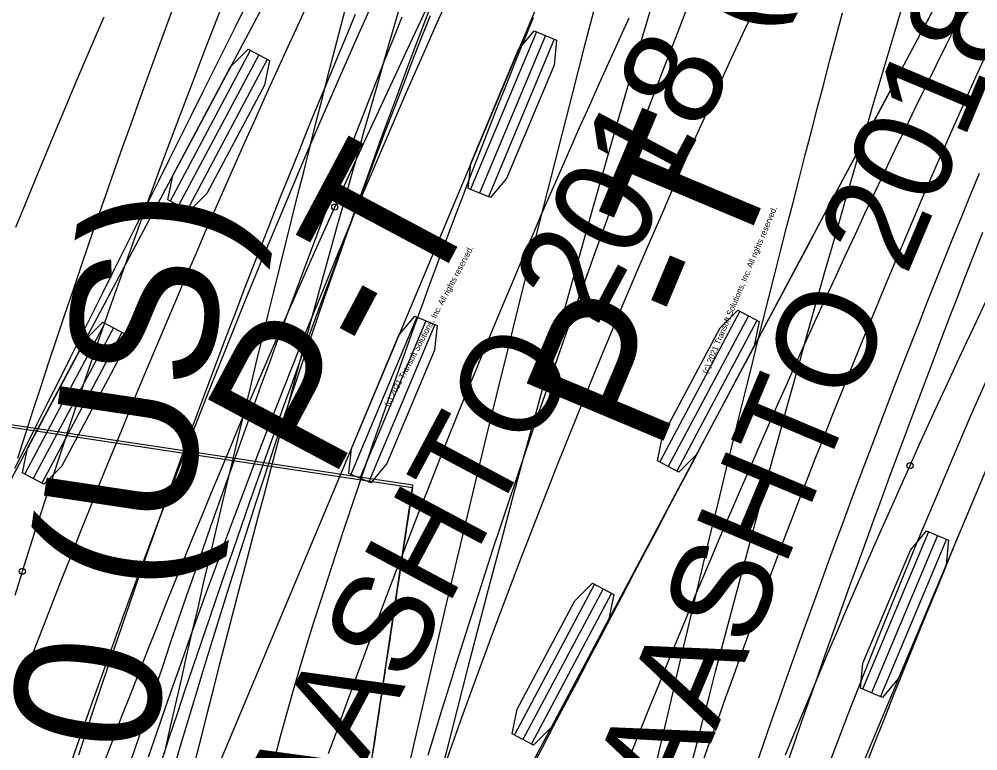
# Model space of a CAD drawing. Extents: x -14 to 1565148, y -25 to 642856.
# Drawn here: x 1564821.96 to 1564834.89, y 636355.96 to 636365.82 of the extents above; entities that cross this region are included whole.
import ezdxf

# ---------------------------------------------------------------- set-up
doc = ezdxf.new("R2010")
doc.units = 0
for name, color, linetype in [('GE_X_Alignment', 7, 'Continuous'), ('MT_P_Drums', 7, 'Continuous'), ('PM_P_Edge_Line', 7, 'Continuous'), ('PV_P_Curb', 7, 'Continuous'), ('PV_P_EOP', 7, 'Continuous'), ('PV_P_Saw_Cut_Line', 7, 'Continuous'), ('PV_X_EOP', 7, 'Continuous'), ('SC_Shading2', 7, 'Continuous'), ('TR_Turning_Path23', 7, 'Continuous'), ('TR_Turning_Path25', 7, 'Continuous'), ('TR_Turning_Path27', 7, 'Continuous')]:
    doc.layers.add(name, color=color, linetype=linetype)

msp = doc.modelspace()

# ---------------------------------------------------------------- linework, layer by layer
at = {"layer": 'GE_X_Alignment'}
for centre, radius, start, end in [((1564912.506, 636333.015), 101.75, 136.94177, 176.98984), ((1564935.682, 636316.638), 107.25, 135.38222, 176.95365)]:
    msp.add_arc(centre, radius, start, end, dxfattribs=at)
at = {"layer": 'MT_P_Drums'}
for points in [[(1564821.945, 636359.902), (1564822.049, 636360.226), (1564822.154, 636360.549), (1564822.26, 636360.872), (1564822.366, 636361.195), (1564822.473, 636361.517), (1564822.581, 636361.839), (1564822.69, 636362.161), (1564822.799, 636362.483), (1564822.91, 636362.805), (1564823.021, 636363.126), (1564823.133, 636363.447), (1564823.245, 636363.768), (1564823.359, 636364.088), (1564823.473, 636364.408), (1564823.587, 636364.728), (1564823.703, 636365.048), (1564823.819, 636365.367), (1564823.937, 636365.686), (1564824.055, 636366.005)], [(1564827.478, 636355.899), (1564827.573, 636356.209), (1564827.668, 636356.519), (1564827.764, 636356.829), (1564827.861, 636357.139), (1564827.959, 636357.448), (1564828.057, 636357.758), (1564828.156, 636358.067), (1564828.256, 636358.375), (1564828.356, 636358.684), (1564828.457, 636358.992), (1564828.559, 636359.3), (1564828.662, 636359.608), (1564828.766, 636359.916), (1564828.87, 636360.223), (1564828.975, 636360.53), (1564829.08, 636360.837), (1564829.187, 636361.144), (1564829.294, 636361.45), (1564829.401, 636361.756), (1564829.51, 636362.062), (1564829.619, 636362.368), (1564829.729, 636362.673), (1564829.84, 636362.978), (1564829.951, 636363.283), (1564830.064, 636363.587), (1564830.177, 636363.891), (1564830.29, 636364.195), (1564830.404, 636364.499), (1564830.52, 636364.803), (1564830.635, 636365.106), (1564830.752, 636365.409), (1564830.869, 636365.711), (1564830.987, 636366.014)], [(1564822.768, 636355.907), (1564822.872, 636356.223), (1564822.977, 636356.539), (1564823.083, 636356.855), (1564823.19, 636357.171), (1564823.297, 636357.486), (1564823.405, 636357.802), (1564823.514, 636358.116), (1564823.623, 636358.431), (1564823.734, 636358.745), (1564823.845, 636359.059), (1564823.957, 636359.373), (1564824.07, 636359.686), (1564824.184, 636359.999), (1564824.298, 636360.312), (1564824.414, 636360.625), (1564824.53, 636360.937), (1564824.647, 636361.249), (1564824.765, 636361.56), (1564824.883, 636361.871), (1564825.003, 636362.182), (1564825.123, 636362.492), (1564825.244, 636362.803), (1564825.366, 636363.112), (1564825.489, 636363.422), (1564825.612, 636363.731), (1564825.737, 636364.04), (1564825.862, 636364.348), (1564825.988, 636364.656), (1564826.115, 636364.964), (1564826.242, 636365.271), (1564826.371, 636365.578), (1564826.5, 636365.885)], [(1564831.177, 636355.797), (1564831.281, 636356.092), (1564831.385, 636356.386), (1564831.491, 636356.681), (1564831.596, 636356.974), (1564831.703, 636357.268), (1564831.81, 636357.561), (1564831.919, 636357.854), (1564832.027, 636358.146), (1564832.137, 636358.438), (1564832.247, 636358.73), (1564832.358, 636359.021), (1564832.47, 636359.312), (1564832.583, 636359.603), (1564832.696, 636359.893), (1564832.81, 636360.183), (1564832.925, 636360.472), (1564833.041, 636360.762), (1564833.157, 636361.05), (1564833.274, 636361.339), (1564833.392, 636361.627), (1564833.511, 636361.914), (1564833.63, 636362.201), (1564833.75, 636362.488), (1564833.871, 636362.774), (1564833.993, 636363.06), (1564834.115, 636363.346), (1564834.238, 636363.631), (1564834.362, 636363.916), (1564834.487, 636364.2), (1564834.612, 636364.484), (1564834.739, 636364.768), (1564834.866, 636365.051), (1564834.993, 636365.334)]]:
    msp.add_lwpolyline(points, dxfattribs=at)
msp.add_arc((1564958.028, 636316.276), 139.668, 153.54197, 168.6689, dxfattribs=at)
at = {"layer": 'PM_P_Edge_Line'}
for p, q in [((1564830.495, 636375.844), (1564817.803, 636352.013)), ((1564824.864, 636348.253), (1564837.556, 636372.084)), ((1564825.079, 636365.397), (1564823.998, 636363.367)), ((1564825.194, 636365.336), (1564824.113, 636363.306)), ((1564825.309, 636365.275), (1564824.227, 636363.245)), ((1564831.68, 636361.882), (1564830.599, 636359.852)), ((1564831.795, 636361.82), (1564830.714, 636359.79)), ((1564831.91, 636361.759), (1564830.829, 636359.729)), ((1564823.12, 636361.72), (1564822.039, 636359.69)), ((1564823.235, 636361.658), (1564822.154, 636359.628)), ((1564823.35, 636361.597), (1564822.269, 636359.567)), ((1564829.722, 636358.204), (1564828.64, 636356.174)), ((1564829.837, 636358.143), (1564828.755, 636356.113)), ((1564829.951, 636358.082), (1564828.87, 636356.052))]:
    msp.add_line(p, q, dxfattribs=at)
for points in [[(1564821.907, 636359.769), (1564822.057, 636360.066), (1564822.207, 636360.364), (1564822.356, 636360.661), (1564822.506, 636360.959), (1564822.655, 636361.257), (1564822.804, 636361.555), (1564822.953, 636361.852), (1564823.102, 636362.15), (1564823.251, 636362.448), (1564823.399, 636362.746), (1564823.548, 636363.044), (1564823.697, 636363.342), (1564823.845, 636363.64), (1564823.994, 636363.938), (1564824.142, 636364.236), (1564824.291, 636364.534), (1564824.439, 636364.832), (1564824.588, 636365.13), (1564824.737, 636365.428), (1564824.886, 636365.725), (1564825.034, 636366.023)], [(1564834.321, 636366.009), (1564834.164, 636365.715), (1564834.008, 636365.421), (1564833.851, 636365.127), (1564833.695, 636364.833), (1564833.538, 636364.539), (1564833.381, 636364.245), (1564833.225, 636363.951), (1564833.068, 636363.657), (1564832.911, 636363.362), (1564832.755, 636363.068), (1564832.598, 636362.774), (1564832.441, 636362.479), (1564832.284, 636362.185), (1564832.127, 636361.89), (1564831.971, 636361.596), (1564831.814, 636361.301), (1564831.657, 636361.007), (1564831.5, 636360.712), (1564831.343, 636360.418), (1564831.186, 636360.123), (1564831.03, 636359.828), (1564830.874, 636359.533), (1564830.719, 636359.238), (1564830.563, 636358.943), (1564830.408, 636358.648), (1564830.252, 636358.352)], [(1564830.252, 636358.352), (1564830.097, 636358.057), (1564829.941, 636357.762), (1564829.786, 636357.467), (1564829.631, 636357.172), (1564829.475, 636356.877), (1564829.319, 636356.582), (1564829.164, 636356.286), (1564829.009, 636355.991), (1564828.853, 636355.696)]]:
    msp.add_lwpolyline(points, dxfattribs=at)
for points in [[(1564825.05, 636365.412), (1564825.337, 636365.26), (1564825.272, 636364.929), (1564824.494, 636363.468), (1564824.256, 636363.23), (1564823.969, 636363.382), (1564824.034, 636363.713), (1564824.812, 636365.174)], [(1564831.652, 636361.897), (1564831.939, 636361.744), (1564831.874, 636361.414), (1564831.095, 636359.952), (1564830.857, 636359.714), (1564830.571, 636359.867), (1564830.635, 636360.197), (1564831.414, 636361.659)], [(1564823.092, 636361.735), (1564823.379, 636361.582), (1564823.314, 636361.252), (1564822.535, 636359.79), (1564822.297, 636359.552), (1564822.011, 636359.705), (1564822.076, 636360.035), (1564822.854, 636361.497)], [(1564829.693, 636358.219), (1564829.98, 636358.066), (1564829.915, 636357.736), (1564829.137, 636356.275), (1564828.899, 636356.036), (1564828.612, 636356.189), (1564828.677, 636356.519), (1564829.455, 636357.981)]]:
    msp.add_lwpolyline(points, close=True, dxfattribs=at)
at = {"layer": 'PV_P_Curb'}
for p, q in [((1564833.368, 636376.548), (1564822.927, 636351.649)), ((1564830.304, 636348.555), (1564840.746, 636373.455)), ((1564828.938, 636365.647), (1564828.048, 636363.526)), ((1564829.058, 636365.596), (1564828.169, 636363.475)), ((1564829.178, 636365.546), (1564828.289, 636363.425)), ((1564827.327, 636361.804), (1564826.437, 636359.683)), ((1564827.447, 636361.754), (1564826.557, 636359.633)), ((1564827.567, 636361.704), (1564826.677, 636359.583)), ((1564827.273, 636359.538), (1564815.623, 636361.29)), ((1564822.99, 636331.058), (1564827.273, 636359.538)), ((1564834.224, 636358.912), (1564833.334, 636356.791)), ((1564834.344, 636358.862), (1564833.454, 636356.741)), ((1564834.464, 636358.811), (1564833.575, 636356.69))]:
    msp.add_line(p, q, dxfattribs=at)
for points in [[(1564823.708, 636355.877), (1564823.819, 636356.202), (1564823.932, 636356.528), (1564824.045, 636356.852), (1564824.16, 636357.177), (1564824.275, 636357.501), (1564824.392, 636357.824), (1564824.509, 636358.148), (1564824.627, 636358.47), (1564824.746, 636358.793), (1564824.866, 636359.115), (1564824.988, 636359.436), (1564825.11, 636359.758), (1564825.232, 636360.078), (1564825.356, 636360.399), (1564825.481, 636360.718), (1564825.607, 636361.038), (1564825.733, 636361.357), (1564825.861, 636361.675), (1564825.989, 636361.993), (1564826.119, 636362.311), (1564826.249, 636362.628), (1564826.38, 636362.945), (1564826.512, 636363.261), (1564826.645, 636363.577), (1564826.779, 636363.892), (1564826.914, 636364.207), (1564827.049, 636364.521), (1564827.186, 636364.835), (1564827.323, 636365.148), (1564827.462, 636365.461), (1564827.601, 636365.774), (1564827.741, 636366.085)], [(1564815.614, 636361.259), (1564827.268, 636359.508), (1564827.252, 636359.401), (1564827.236, 636359.294), (1564827.22, 636359.186), (1564827.203, 636359.078), (1564827.187, 636358.97), (1564827.171, 636358.862), (1564827.155, 636358.754), (1564827.138, 636358.647), (1564827.122, 636358.538), (1564827.106, 636358.43), (1564827.09, 636358.321), (1564827.073, 636358.213), (1564827.057, 636358.104), (1564827.041, 636357.995), (1564827.024, 636357.886), (1564827.008, 636357.777), (1564826.991, 636357.668), (1564826.975, 636357.559), (1564826.959, 636357.45), (1564826.942, 636357.341), (1564826.926, 636357.232), (1564826.909, 636357.122), (1564826.893, 636357.013), (1564826.876, 636356.904), (1564826.86, 636356.794), (1564826.844, 636356.685), (1564826.827, 636356.576), (1564826.811, 636356.466), (1564826.794, 636356.357), (1564826.778, 636356.247), (1564826.761, 636356.138), (1564826.745, 636356.028), (1564826.728, 636355.919)], [(1564834.968, 636359.677), (1564834.843, 636359.377), (1564834.718, 636359.078), (1564834.593, 636358.779), (1564834.469, 636358.479), (1564834.346, 636358.179), (1564834.223, 636357.879), (1564834.101, 636357.579), (1564833.98, 636357.279), (1564833.859, 636356.979), (1564833.738, 636356.678), (1564833.618, 636356.378), (1564833.499, 636356.077), (1564833.38, 636355.776)]]:
    msp.add_lwpolyline(points, dxfattribs=at)
for points in [[(1564828.908, 636365.659), (1564829.208, 636365.534), (1564829.174, 636365.199), (1564828.533, 636363.672), (1564828.318, 636363.413), (1564828.019, 636363.538), (1564828.053, 636363.873), (1564828.693, 636365.4)], [(1564827.297, 636361.817), (1564827.597, 636361.691), (1564827.562, 636361.356), (1564826.922, 636359.829), (1564826.707, 636359.57), (1564826.407, 636359.696), (1564826.442, 636360.031), (1564827.082, 636361.558)], [(1564834.194, 636358.924), (1564834.494, 636358.799), (1564834.46, 636358.464), (1564833.819, 636356.937), (1564833.604, 636356.678), (1564833.305, 636356.803), (1564833.339, 636357.138), (1564833.979, 636358.665)]]:
    msp.add_lwpolyline(points, close=True, dxfattribs=at)
msp.add_arc((1564933.467, 636318.397), 112.174, 151.79375, 166.73062, dxfattribs=at)
at = {"layer": 'PV_P_EOP'}
for centre, radius, start, end in [((1564912.506, 636333.015), 101.75, 136.94177, 176.99004), ((1564912.506, 636333.015), 101, 136.94177, 176.99004), ((1564935.682, 636316.638), 108, 135.38222, 176.99233), ((1564935.682, 636316.638), 107.25, 135.38222, 176.99233)]:
    msp.add_arc(centre, radius, start, end, dxfattribs=at)
at = {"layer": 'PV_P_Saw_Cut_Line'}
for points in [[(1564823.922, 636355.919), (1564823.997, 636356.247), (1564824.072, 636356.576), (1564824.147, 636356.904), (1564824.222, 636357.232), (1564824.298, 636357.56), (1564824.375, 636357.888), (1564824.451, 636358.216), (1564824.528, 636358.544), (1564824.605, 636358.872), (1564824.683, 636359.2), (1564824.761, 636359.527), (1564824.839, 636359.855), (1564824.918, 636360.182), (1564824.996, 636360.51), (1564825.076, 636360.837), (1564825.155, 636361.164), (1564825.235, 636361.491), (1564825.315, 636361.818), (1564825.396, 636362.145), (1564825.477, 636362.472), (1564825.558, 636362.799), (1564825.64, 636363.126), (1564825.721, 636363.453), (1564825.804, 636363.779), (1564825.886, 636364.106), (1564825.969, 636364.432), (1564826.052, 636364.758), (1564826.136, 636365.085), (1564826.22, 636365.411), (1564826.304, 636365.737), (1564826.389, 636366.063)], [(1564830.523, 636355.649), (1564830.598, 636355.971), (1564830.672, 636356.292), (1564830.747, 636356.614), (1564830.822, 636356.935), (1564830.898, 636357.257), (1564830.974, 636357.578), (1564831.05, 636357.899), (1564831.127, 636358.22), (1564831.204, 636358.542), (1564831.281, 636358.863), (1564831.358, 636359.184), (1564831.436, 636359.504), (1564831.514, 636359.825), (1564831.593, 636360.146), (1564831.672, 636360.466), (1564831.751, 636360.787), (1564831.831, 636361.107), (1564831.91, 636361.428), (1564831.991, 636361.748), (1564832.071, 636362.068), (1564832.152, 636362.388), (1564832.233, 636362.709), (1564832.314, 636363.029), (1564832.396, 636363.348), (1564832.478, 636363.668), (1564832.561, 636363.988), (1564832.644, 636364.308), (1564832.727, 636364.627), (1564832.81, 636364.947), (1564832.894, 636365.266), (1564832.978, 636365.585), (1564833.062, 636365.904)], [(1564823.476, 636355.832), (1564823.581, 636356.149), (1564823.687, 636356.465), (1564823.792, 636356.781), (1564823.899, 636357.097), (1564824.006, 636357.412), (1564824.114, 636357.728), (1564824.222, 636358.043), (1564824.331, 636358.358), (1564824.44, 636358.673), (1564824.55, 636358.988), (1564824.661, 636359.302), (1564824.772, 636359.616), (1564824.883, 636359.931), (1564824.996, 636360.244), (1564825.109, 636360.558), (1564825.222, 636360.871), (1564825.337, 636361.184), (1564825.452, 636361.497), (1564825.567, 636361.81), (1564825.683, 636362.122), (1564825.8, 636362.435), (1564825.918, 636362.746), (1564826.036, 636363.058), (1564826.154, 636363.369), (1564826.274, 636363.681), (1564826.394, 636363.991), (1564826.515, 636364.302), (1564826.636, 636364.612), (1564826.758, 636364.922), (1564826.881, 636365.232), (1564827.005, 636365.542), (1564827.129, 636365.851)], [(1564831.893, 636355.747), (1564831.997, 636356.048), (1564832.102, 636356.349), (1564832.208, 636356.649), (1564832.314, 636356.949), (1564832.42, 636357.248), (1564832.527, 636357.547), (1564832.635, 636357.846), (1564832.743, 636358.144), (1564832.852, 636358.442), (1564832.961, 636358.74), (1564833.071, 636359.037), (1564833.182, 636359.334), (1564833.293, 636359.631), (1564833.404, 636359.927), (1564833.516, 636360.223), (1564833.629, 636360.518), (1564833.742, 636360.813), (1564833.856, 636361.108), (1564833.971, 636361.402), (1564834.086, 636361.696), (1564834.201, 636361.99), (1564834.318, 636362.283), (1564834.435, 636362.575), (1564834.552, 636362.868), (1564834.67, 636363.16), (1564834.789, 636363.451), (1564834.908, 636363.742)]]:
    msp.add_lwpolyline(points, dxfattribs=at)
msp.add_arc((1565146.749, 636282.802), 327.756, 163.72284, 170.42683, dxfattribs=at)
at = {"layer": 'PV_X_EOP'}
msp.add_arc((1564935.678, 636316.634), 110, 135.38222, 176.99004, dxfattribs=at)
at = {"layer": 'SC_Shading2'}
msp.add_ellipse((1564935.682, 636316.638), major_axis=(103.369, -29.517), ratio=0.999149, start_param=2.887636, end_param=3.387039, dxfattribs=at)
at = {"layer": 'TR_Turning_Path23'}
for points in [[(1564824.338, 636355.819), (1564824.421, 636356.147), (1564824.504, 636356.475), (1564824.587, 636356.803), (1564824.671, 636357.13), (1564824.756, 636357.458), (1564824.84, 636357.785), (1564824.925, 636358.113), (1564825.011, 636358.44), (1564825.097, 636358.767), (1564825.183, 636359.094), (1564825.27, 636359.421), (1564825.357, 636359.748), (1564825.444, 636360.074), (1564825.532, 636360.401), (1564825.62, 636360.727), (1564825.709, 636361.054), (1564825.798, 636361.38), (1564825.887, 636361.706), (1564825.977, 636362.032), (1564826.067, 636362.358), (1564826.157, 636362.684), (1564826.248, 636363.01), (1564826.339, 636363.335), (1564826.431, 636363.661), (1564826.523, 636363.986), (1564826.616, 636364.311), (1564826.709, 636364.637), (1564826.802, 636364.962), (1564826.895, 636365.287), (1564826.989, 636365.611), (1564827.084, 636365.936)], [(1564831.02, 636355.747), (1564831.103, 636356.066), (1564831.186, 636356.386), (1564831.27, 636356.706), (1564831.353, 636357.026), (1564831.437, 636357.345), (1564831.522, 636357.665), (1564831.607, 636357.984), (1564831.692, 636358.303), (1564831.778, 636358.622), (1564831.864, 636358.942), (1564831.95, 636359.26), (1564832.037, 636359.579), (1564832.125, 636359.898), (1564832.212, 636360.217), (1564832.3, 636360.535), (1564832.388, 636360.854), (1564832.477, 636361.172), (1564832.566, 636361.49), (1564832.656, 636361.808), (1564832.746, 636362.126), (1564832.836, 636362.444), (1564832.926, 636362.762), (1564833.017, 636363.079), (1564833.109, 636363.397), (1564833.201, 636363.714), (1564833.293, 636364.032), (1564833.385, 636364.349), (1564833.478, 636364.666), (1564833.571, 636364.983), (1564833.665, 636365.3), (1564833.759, 636365.617), (1564833.854, 636365.933)], [(1564823.887, 636355.83), (1564823.992, 636356.147), (1564824.098, 636356.463), (1564824.204, 636356.779), (1564824.311, 636357.094), (1564824.418, 636357.41), (1564824.526, 636357.726), (1564824.634, 636358.041), (1564824.742, 636358.356), (1564824.852, 636358.671), (1564824.961, 636358.986), (1564825.071, 636359.301), (1564825.182, 636359.616), (1564825.293, 636359.93), (1564825.404, 636360.244), (1564825.516, 636360.558), (1564825.629, 636360.872), (1564825.742, 636361.186), (1564825.856, 636361.5), (1564825.97, 636361.813), (1564826.085, 636362.126), (1564826.2, 636362.439), (1564826.316, 636362.752), (1564826.433, 636363.064), (1564826.55, 636363.377), (1564826.667, 636363.689), (1564826.785, 636364.001), (1564826.904, 636364.312), (1564827.023, 636364.624), (1564827.143, 636364.935), (1564827.264, 636365.246), (1564827.385, 636365.557), (1564827.507, 636365.868)], [(1564832.306, 636355.751), (1564832.412, 636356.055), (1564832.517, 636356.358), (1564832.623, 636356.661), (1564832.729, 636356.963), (1564832.836, 636357.266), (1564832.943, 636357.568), (1564833.051, 636357.869), (1564833.159, 636358.171), (1564833.268, 636358.472), (1564833.377, 636358.772), (1564833.486, 636359.073), (1564833.596, 636359.373), (1564833.707, 636359.673), (1564833.818, 636359.972), (1564833.929, 636360.271), (1564834.041, 636360.57), (1564834.153, 636360.868), (1564834.266, 636361.166), (1564834.38, 636361.464), (1564834.494, 636361.762), (1564834.608, 636362.059), (1564834.723, 636362.356), (1564834.839, 636362.652), (1564834.955, 636362.948)]]:
    msp.add_lwpolyline(points, dxfattribs=at)
msp.add_arc((1565099.324, 636286.618), 280.312, 161.13509, 168.78836, dxfattribs=at)
at = {"layer": 'TR_Turning_Path25'}
for points in [[(1564830.12, 636355.688), (1564830.237, 636355.981), (1564830.354, 636356.274), (1564830.471, 636356.567), (1564830.59, 636356.859), (1564830.709, 636357.151), (1564830.829, 636357.443), (1564830.949, 636357.734), (1564831.07, 636358.025), (1564831.192, 636358.316), (1564831.315, 636358.606), (1564831.438, 636358.896), (1564831.562, 636359.186), (1564831.686, 636359.475), (1564831.812, 636359.764), (1564831.938, 636360.053), (1564832.065, 636360.342), (1564832.192, 636360.63), (1564832.32, 636360.917), (1564832.449, 636361.205), (1564832.578, 636361.492), (1564832.709, 636361.779), (1564832.839, 636362.065), (1564832.971, 636362.351), (1564833.103, 636362.637), (1564833.236, 636362.922), (1564833.37, 636363.207), (1564833.504, 636363.492), (1564833.639, 636363.776), (1564833.775, 636364.06), (1564833.912, 636364.344), (1564834.049, 636364.627), (1564834.186, 636364.91), (1564834.325, 636365.192), (1564834.464, 636365.474), (1564834.604, 636365.756), (1564834.745, 636366.038)], [(1564821.952, 636356.748), (1564822.071, 636357.06), (1564822.191, 636357.373), (1564822.311, 636357.685), (1564822.432, 636357.997), (1564822.554, 636358.309), (1564822.677, 636358.62), (1564822.8, 636358.931), (1564822.924, 636359.242), (1564823.049, 636359.552), (1564823.175, 636359.862), (1564823.301, 636360.172), (1564823.428, 636360.482), (1564823.556, 636360.791), (1564823.685, 636361.1), (1564823.814, 636361.408), (1564823.944, 636361.717), (1564824.075, 636362.024), (1564824.206, 636362.332), (1564824.339, 636362.639), (1564824.472, 636362.946), (1564824.606, 636363.253), (1564824.74, 636363.559), (1564824.875, 636363.865), (1564825.012, 636364.171), (1564825.148, 636364.476), (1564825.286, 636364.781), (1564825.424, 636365.086), (1564825.563, 636365.39), (1564825.703, 636365.694), (1564825.843, 636365.998)], [(1564821.921, 636363.014), (1564822.05, 636363.331), (1564822.179, 636363.647), (1564822.31, 636363.963), (1564822.441, 636364.279), (1564822.574, 636364.594), (1564822.707, 636364.909), (1564822.841, 636365.223), (1564822.975, 636365.538), (1564823.111, 636365.851)], [(1564826.136, 636355.921), (1564826.245, 636356.226), (1564826.356, 636356.531), (1564826.468, 636356.836), (1564826.58, 636357.141), (1564826.693, 636357.445), (1564826.807, 636357.749), (1564826.922, 636358.053), (1564827.038, 636358.356), (1564827.154, 636358.659), (1564827.272, 636358.962), (1564827.39, 636359.264), (1564827.508, 636359.567), (1564827.628, 636359.868), (1564827.749, 636360.17), (1564827.87, 636360.471), (1564827.992, 636360.772), (1564828.115, 636361.072), (1564828.238, 636361.373), (1564828.363, 636361.672), (1564828.488, 636361.972), (1564828.614, 636362.271), (1564828.741, 636362.57), (1564828.869, 636362.868), (1564828.997, 636363.167), (1564829.127, 636363.464), (1564829.257, 636363.762), (1564829.387, 636364.059), (1564829.519, 636364.356), (1564829.651, 636364.652), (1564829.785, 636364.948), (1564829.919, 636365.244), (1564830.053, 636365.539), (1564830.189, 636365.834)]]:
    msp.add_lwpolyline(points, dxfattribs=at)
msp.add_arc((1564940.689, 636314.867), 124.922, 128.00393, 166.21829, dxfattribs=at)
at = {"layer": 'TR_Turning_Path27'}
for points in [[(1564826.219, 636363.285), (1564826.352, 636363.58), (1564826.486, 636363.875), (1564826.621, 636364.17), (1564826.757, 636364.465), (1564826.893, 636364.759), (1564827.031, 636365.054), (1564827.169, 636365.348), (1564827.308, 636365.643), (1564827.448, 636365.937)], [(1564825.41, 636355.862), (1564825.491, 636356.169), (1564825.575, 636356.476), (1564825.661, 636356.781), (1564825.75, 636357.085), (1564825.842, 636357.388), (1564825.938, 636357.694), (1564826.035, 636357.995), (1564826.134, 636358.301), (1564826.234, 636358.606), (1564826.334, 636358.911), (1564826.436, 636359.216), (1564826.539, 636359.521), (1564826.642, 636359.825), (1564826.747, 636360.129), (1564826.852, 636360.432), (1564826.958, 636360.735), (1564827.065, 636361.038), (1564827.173, 636361.341), (1564827.282, 636361.643), (1564827.391, 636361.945), (1564827.502, 636362.247), (1564827.613, 636362.548), (1564827.725, 636362.849), (1564827.838, 636363.15), (1564827.952, 636363.45), (1564828.067, 636363.75), (1564828.183, 636364.05), (1564828.3, 636364.349), (1564828.417, 636364.648), (1564828.536, 636364.947), (1564828.655, 636365.245), (1564828.775, 636365.543), (1564828.896, 636365.841)], [(1564823.118, 636355.823), (1564823.234, 636356.125), (1564823.35, 636356.427), (1564823.468, 636356.729), (1564823.585, 636357.03), (1564823.704, 636357.331), (1564823.823, 636357.632), (1564823.943, 636357.932), (1564824.064, 636358.232), (1564824.185, 636358.532), (1564824.307, 636358.832), (1564824.43, 636359.131), (1564824.553, 636359.43), (1564824.677, 636359.729), (1564824.802, 636360.027), (1564824.927, 636360.325), (1564825.053, 636360.622), (1564825.18, 636360.92), (1564825.308, 636361.216), (1564825.436, 636361.513), (1564825.565, 636361.809), (1564825.694, 636362.105), (1564825.824, 636362.401), (1564825.955, 636362.696), (1564826.087, 636362.991), (1564826.219, 636363.285)], [(1564833.973, 636359.803), (1564834.098, 636360.08), (1564834.223, 636360.356), (1564834.35, 636360.632), (1564834.477, 636360.908), (1564834.605, 636361.184), (1564834.734, 636361.46), (1564834.863, 636361.736), (1564834.994, 636362.012)], [(1564832.294, 636355.907), (1564832.41, 636356.187), (1564832.527, 636356.467), (1564832.644, 636356.747), (1564832.761, 636357.027), (1564832.88, 636357.306), (1564832.999, 636357.585), (1564833.118, 636357.863), (1564833.238, 636358.142), (1564833.359, 636358.42), (1564833.481, 636358.697), (1564833.603, 636358.974), (1564833.726, 636359.251), (1564833.849, 636359.527), (1564833.973, 636359.803)], [(1564821.909, 636358.058), (1564822.007, 636358.376)]]:
    msp.add_lwpolyline(points, dxfattribs=at)
for centre in [(1564826.219, 636363.285), (1564826.219, 636363.285), (1564833.973, 636359.803), (1564833.973, 636359.803), (1564822.007, 636358.376), (1564822.007, 636358.376)]:
    msp.add_circle(centre, 0.0417, dxfattribs=at)
msp.add_arc((1564931.179, 636324.092), 114.429, 128.5803, 162.56557, dxfattribs=at)

# ---------------------------------------------------------------- texts
at = {"layer": 'PM_P_Edge_Line'}
for s, height, p in [('AASHTO 2018 (US)', 1.33333, (1564826.06, 636354.738)), ('P-T', 2, (1564826.173, 636359.56)), ('(c) 2021 Transoft Solutions, Inc. All rights reserved.', 0.08, (1564826.949, 636360.59))]:
    msp.add_text(s, height=height, rotation=61.9621, dxfattribs=at).set_placement(p)
at = {"layer": 'PV_P_Curb'}
for s, height, rotation, p in [('AASHTO 2018 (US)', 1.33333, 67.2494, (1564830.897, 636355.123)), ('P-T', 2, 67.2494, (1564830.565, 636359.935)), ('WisDOT OSOW 2010 (US)', 1.96333, 81.4485, (1564820.175, 636332.075)), ('(c) 2021 Transoft Solutions, Inc. All rights reserved.', 0.08, 67.2494, (1564831.243, 636361.033))]:
    msp.add_text(s, height=height, rotation=rotation, dxfattribs=at).set_placement(p)

doc.saveas('drawing.dxf')
